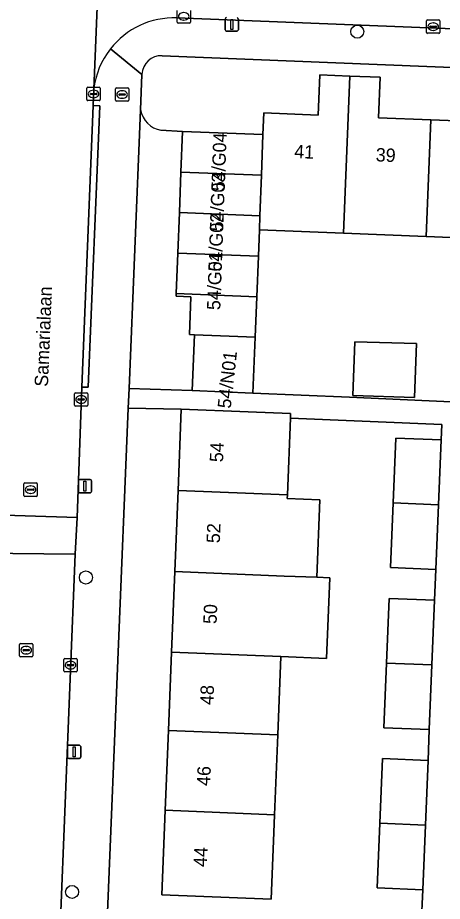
# Model space of a CAD drawing. Extents: x 161354 to 162026, y 386504 to 387460.
# Drawn here: x 161514.1 to 161545.9, y 387060.8 to 387126.9 of the extents above; entities that cross this region are included whole.
import ezdxf

# ---------------------------------------------------------------- set-up
doc = ezdxf.new("R2010")
doc.units = 0
for name, color, linetype in [('IMGEO_Boom', 7, 'Continuous'), ('IMGEO_Brandkraan', 7, 'Continuous'), ('IMGEO_Erf', 7, 'Continuous'), ('IMGEO_Kolk', 7, 'Continuous'), ('IMGEO_Lichtmast', 7, 'Continuous'), ('IMGEO_Openbare_ruimte_label', 7, 'Continuous'), ('IMGEO_Pand', 7, 'Continuous'), ('IMGEO_Pand_nummerreeks', 7, 'Continuous'), ('IMGEO_Rijbaan_lokaal_open', 7, 'Continuous'), ('IMGEO_Rioolput', 7, 'Continuous'), ('IMGEO_Voetpad_open', 7, 'Continuous')]:
    doc.layers.add(name, color=color, linetype=linetype)

msp = doc.modelspace()

# ---------------------------------------------------------------- linework, layer by layer
at = {"layer": 'IMGEO_Boom'}
for centre in [(161539.507, 387125.881), (161519.186, 387085.044), (161518.148, 387061.52)]:
    msp.add_circle(centre, 0.489, dxfattribs=at)
at = {"layer": 'IMGEO_Brandkraan'}
for p, q in [((161521.471, 387121.677), (161522.323, 387121.677)), ((161521.396, 387120.751), (161521.396, 387121.603)), ((161521.655, 387121.171), (161521.655, 387121.183)), ((161522.093, 387121.134), (161521.695, 387121.134)), ((161521.698, 387121.22), (161522.096, 387121.22)), ((161521.884, 387121.457), (161521.909, 387121.457)), ((161522.139, 387121.183), (161522.139, 387121.171)), ((161522.397, 387121.603), (161522.397, 387120.751)), ((161522.323, 387120.677), (161521.471, 387120.677)), ((161521.907, 387120.897), (161521.882, 387120.897))]:
    msp.add_line(p, q, dxfattribs=at)
for points in [[(161521.471, 387121.677), (161522.323, 387121.677)], [(161521.396, 387120.751), (161521.396, 387121.603)], [(161522.397, 387121.603), (161522.397, 387120.751)], [(161522.323, 387120.677), (161521.471, 387120.677)]]:
    msp.add_lwpolyline(points, dxfattribs=at)
for centre, radius, start, end in [((161521.473, 387121.601), 0.0765, 91.55205, 178.44795), ((161521.473, 387121.601), 0.0765, 91.55205, 178.44795), ((161522.321, 387121.601), 0.0765, 1.55205, 88.44795), ((161522.321, 387121.601), 0.0765, 1.55205, 88.44795), ((161521.695, 387121.18), 0.0403, 85.87752, 175.75265), ((161521.692, 387121.17), 0.0366, 178.93798, 274.71019), ((161522.096, 387121.177), 0.043, 264.86636, 352.45326), ((161522.1, 387121.182), 0.0386, 1.73085, 96.63898), ((161521.473, 387120.753), 0.0765, 181.55205, 268.44795), ((161521.473, 387120.753), 0.0765, 181.55205, 268.44795), ((161522.321, 387120.753), 0.0765, 271.55205, 358.44795), ((161522.321, 387120.753), 0.0765, 271.55205, 358.44795)]:
    msp.add_arc(centre, radius, start, end, dxfattribs=at)
for centre, major_axis, ratio, start_param, end_param in [((161521.883, 387121.177), (-0.387, 0.002), 0.722429, 4.712389, 7.853982), ((161521.908, 387121.177), (-0.39, 0.002), 0.717154, 1.570796, 4.712389)]:
    msp.add_ellipse(centre, major_axis=major_axis, ratio=ratio, start_param=start_param, end_param=end_param, dxfattribs=at)
at = {"layer": 'IMGEO_Erf'}
for points in [[(161607.248, 387120.747), (161524.9, 387124.083)], [(161523.384, 387122.688), (161523.275, 387120.032)], [(161524.801, 387118.502), (161526.428, 387118.418), (161532.445, 387118.176), (161532.513, 387119.807), (161536.573, 387119.644), (161536.694, 387122.652), (161538.952, 387122.561), (161541.209, 387122.47), (161541.087, 387119.445), (161545.005, 387119.288), (161548.923, 387119.13), (161549.045, 387122.166), (161551.292, 387122.075), (161553.539, 387121.985), (161553.417, 387118.951), (161557.35, 387118.793), (161561.284, 387118.635), (161561.407, 387121.696)], [(161581.68, 387109.068), (161575.525, 387109.316), (161569.368, 387109.563), (161563.19, 387109.812), (161556.999, 387110.061), (161554.637, 387110.156), (161554.514, 387107.096), (161550.695, 387107.25), (161550.818, 387110.309), (161544.654, 387110.557), (161538.479, 387110.806), (161532.18, 387111.059), (161532.101, 387109.083), (161531.979, 387106.052), (161531.857, 387103.021), (161531.689, 387098.848), (161538.919, 387098.528), (161547.059, 387098.161), (161547.177, 387101.182), (161550.075, 387101.069), (161549.957, 387098.047), (161567.776, 387097.249), (161585.787, 387096.692)], [(161544.294, 387059.047), (161544.402, 387061.685), (161541.005, 387061.824), (161541.204, 387066.661), (161541.403, 387071.507), (161544.8, 387071.368), (161544.894, 387073.666), (161541.497, 387073.806), (161541.695, 387078.643), (161541.894, 387083.478), (161545.291, 387083.339), (161545.386, 387085.648), (161541.989, 387085.787), (161542.187, 387090.627), (161542.386, 387095.473), (161545.783, 387095.333), (161545.831, 387096.504), (161534.5, 387096.963), (161534.27, 387091.239), (161534.259, 387090.964), (161536.71, 387090.866), (161536.477, 387085.059), (161537.45, 387085.02), (161537.209, 387078.993), (161533.785, 387079.13), (161533.55, 387073.273), (161533.311, 387067.302), (161533.258, 387065.977), (161533.058, 387060.981), (161524.876, 387061.309), (161525.129, 387067.63), (161525.368, 387073.601), (161525.603, 387079.458), (161525.844, 387085.485), (161526.088, 387091.567), (161526.331, 387097.645), (161522.356, 387097.725), (161520.801, 387060.002)]]:
    msp.add_lwpolyline(points, dxfattribs=at)
msp.add_lwpolyline([(161543.779, 387098.504), (161539.175, 387098.672), (161539.321, 387102.683), (161543.927, 387102.555)], close=True, dxfattribs=at)
for centre, radius, start, end in [((161524.84, 387122.627), 1.457, 87.64736, 177.59221), ((161525.138, 387120.364), 1.893, 190.11447, 259.73554)]:
    msp.add_arc(centre, radius, start, end, dxfattribs=at)
at = {"layer": 'IMGEO_Kolk'}
for p, q in [((161526.013, 387126.602), (161526.013, 387127.454)), ((161527.014, 387127.454), (161527.014, 387126.602)), ((161526.94, 387126.528), (161526.088, 387126.528)), ((161526.524, 387126.748), (161526.499, 387126.748)), ((161544.689, 387125.83), (161544.689, 387126.682)), ((161544.764, 387126.756), (161545.616, 387126.756)), ((161544.948, 387126.25), (161544.948, 387126.262)), ((161544.991, 387126.299), (161545.389, 387126.299)), ((161545.177, 387126.536), (161545.202, 387126.536)), ((161545.432, 387126.262), (161545.432, 387126.25)), ((161545.69, 387126.682), (161545.69, 387125.83)), ((161545.616, 387125.756), (161544.764, 387125.756)), ((161545.386, 387126.213), (161544.988, 387126.213)), ((161545.2, 387125.976), (161545.175, 387125.976)), ((161519.26, 387120.795), (161519.26, 387121.647)), ((161519.335, 387121.721), (161520.187, 387121.721)), ((161520.261, 387121.647), (161520.261, 387120.795)), ((161519.519, 387121.215), (161519.519, 387121.227)), ((161519.957, 387121.178), (161519.559, 387121.178)), ((161519.562, 387121.264), (161519.96, 387121.264)), ((161519.748, 387121.501), (161519.773, 387121.501)), ((161520.003, 387121.227), (161520.003, 387121.215)), ((161520.187, 387120.721), (161519.335, 387120.721)), ((161519.771, 387120.941), (161519.746, 387120.941)), ((161518.329, 387097.941), (161518.329, 387098.793)), ((161518.404, 387098.867), (161519.256, 387098.867)), ((161518.817, 387098.647), (161518.842, 387098.647)), ((161519.33, 387098.793), (161519.33, 387097.941)), ((161519.256, 387097.867), (161518.404, 387097.867)), ((161518.588, 387098.361), (161518.588, 387098.373)), ((161519.026, 387098.324), (161518.628, 387098.324)), ((161518.631, 387098.41), (161519.029, 387098.41)), ((161518.84, 387098.087), (161518.815, 387098.087)), ((161519.072, 387098.373), (161519.072, 387098.361)), ((161517.533, 387078.067), (161517.533, 387078.919)), ((161517.608, 387078.993), (161518.46, 387078.993)), ((161518.021, 387078.773), (161518.046, 387078.773)), ((161518.534, 387078.919), (161518.534, 387078.067)), ((161518.46, 387077.993), (161517.608, 387077.993)), ((161517.792, 387078.487), (161517.792, 387078.499)), ((161518.23, 387078.45), (161517.832, 387078.45)), ((161517.835, 387078.536), (161518.233, 387078.536)), ((161518.044, 387078.213), (161518.019, 387078.213)), ((161518.276, 387078.499), (161518.276, 387078.487))]:
    msp.add_line(p, q, dxfattribs=at)
for points in [[(161526.013, 387126.602), (161526.013, 387127.454)], [(161527.014, 387127.454), (161527.014, 387126.602)], [(161526.94, 387126.528), (161526.088, 387126.528)], [(161544.689, 387125.83), (161544.689, 387126.682)], [(161544.764, 387126.756), (161545.616, 387126.756)], [(161545.69, 387126.682), (161545.69, 387125.83)], [(161545.616, 387125.756), (161544.764, 387125.756)], [(161519.26, 387120.795), (161519.26, 387121.647)], [(161519.335, 387121.721), (161520.187, 387121.721)], [(161520.261, 387121.647), (161520.261, 387120.795)], [(161520.187, 387120.721), (161519.335, 387120.721)], [(161518.329, 387097.941), (161518.329, 387098.793)], [(161518.404, 387098.867), (161519.256, 387098.867)], [(161519.33, 387098.793), (161519.33, 387097.941)], [(161519.256, 387097.867), (161518.404, 387097.867)], [(161517.533, 387078.067), (161517.533, 387078.919)], [(161517.608, 387078.993), (161518.46, 387078.993)], [(161518.534, 387078.919), (161518.534, 387078.067)], [(161518.46, 387077.993), (161517.608, 387077.993)]]:
    msp.add_lwpolyline(points, dxfattribs=at)
for centre, radius, start, end in [((161526.09, 387126.604), 0.0765, 181.55205, 268.44795), ((161526.09, 387126.604), 0.0765, 181.55205, 268.44795), ((161526.938, 387126.604), 0.0765, 271.55205, 358.44795), ((161526.938, 387126.604), 0.0765, 271.55205, 358.44795), ((161544.766, 387126.68), 0.0765, 91.55205, 178.44795), ((161544.766, 387126.68), 0.0765, 91.55205, 178.44795), ((161544.988, 387126.259), 0.0403, 85.87752, 175.75265), ((161544.985, 387126.249), 0.0366, 178.93798, 274.71019), ((161545.389, 387126.256), 0.043, 264.86636, 352.45326), ((161545.393, 387126.261), 0.0386, 1.73085, 96.63898), ((161545.614, 387126.68), 0.0765, 1.55205, 88.44795), ((161545.614, 387126.68), 0.0765, 1.55205, 88.44795), ((161544.766, 387125.832), 0.0765, 181.55205, 268.44795), ((161544.766, 387125.832), 0.0765, 181.55205, 268.44795), ((161545.614, 387125.832), 0.0765, 271.55205, 358.44795), ((161545.614, 387125.832), 0.0765, 271.55205, 358.44795), ((161519.337, 387121.645), 0.0765, 91.55205, 178.44795), ((161519.337, 387121.645), 0.0765, 91.55205, 178.44795), ((161520.185, 387121.645), 0.0765, 1.55205, 88.44795), ((161520.185, 387121.645), 0.0765, 1.55205, 88.44795), ((161519.559, 387121.224), 0.0403, 85.87752, 175.75265), ((161519.556, 387121.214), 0.0366, 178.93798, 274.71019), ((161519.96, 387121.221), 0.043, 264.86636, 352.45326), ((161519.964, 387121.226), 0.0386, 1.73085, 96.63898), ((161519.337, 387120.797), 0.0765, 181.55205, 268.44795), ((161519.337, 387120.797), 0.0765, 181.55205, 268.44795), ((161520.185, 387120.797), 0.0765, 271.55205, 358.44795), ((161520.185, 387120.797), 0.0765, 271.55205, 358.44795), ((161518.406, 387098.791), 0.0765, 91.55205, 178.44795), ((161518.406, 387098.791), 0.0765, 91.55205, 178.44795), ((161519.254, 387098.791), 0.0765, 1.55205, 88.44795), ((161519.254, 387098.791), 0.0765, 1.55205, 88.44795), ((161518.406, 387097.943), 0.0765, 181.55205, 268.44795), ((161518.406, 387097.943), 0.0765, 181.55205, 268.44795), ((161518.628, 387098.37), 0.0403, 85.87752, 175.75265), ((161518.625, 387098.36), 0.0366, 178.93798, 274.71019), ((161519.029, 387098.367), 0.043, 264.86636, 352.45326), ((161519.033, 387098.372), 0.0386, 1.73085, 96.63898), ((161519.254, 387097.943), 0.0765, 271.55205, 358.44795), ((161519.254, 387097.943), 0.0765, 271.55205, 358.44795), ((161517.61, 387078.917), 0.0765, 91.55205, 178.44795), ((161517.61, 387078.917), 0.0765, 91.55205, 178.44795), ((161518.458, 387078.917), 0.0765, 1.55205, 88.44795), ((161518.458, 387078.917), 0.0765, 1.55205, 88.44795), ((161517.61, 387078.069), 0.0765, 181.55205, 268.44795), ((161517.61, 387078.069), 0.0765, 181.55205, 268.44795), ((161517.832, 387078.496), 0.0403, 85.87752, 175.75265), ((161517.829, 387078.486), 0.0366, 178.93798, 274.71019), ((161518.233, 387078.493), 0.043, 264.86636, 352.45326), ((161518.237, 387078.498), 0.0386, 1.73085, 96.63898), ((161518.458, 387078.069), 0.0765, 271.55205, 358.44795), ((161518.458, 387078.069), 0.0765, 271.55205, 358.44795)]:
    msp.add_arc(centre, radius, start, end, dxfattribs=at)
for centre, major_axis, ratio, start_param, end_param in [((161526.5, 387127.028), (-0.387, 0.002), 0.722429, 4.712389, 7.853982), ((161526.525, 387127.028), (-0.39, 0.002), 0.717154, 1.570796, 4.712389), ((161545.176, 387126.256), (-0.387, 0.002), 0.722429, 4.712389, 7.853982), ((161545.201, 387126.256), (-0.39, 0.002), 0.717154, 1.570796, 4.712389), ((161519.747, 387121.221), (-0.387, 0.002), 0.722429, 4.712389, 7.853982), ((161519.772, 387121.221), (-0.39, 0.002), 0.717154, 1.570796, 4.712389), ((161518.816, 387098.367), (-0.387, 0.002), 0.722429, 4.712389, 7.853982), ((161518.841, 387098.367), (-0.39, 0.002), 0.717154, 1.570796, 4.712389), ((161518.02, 387078.493), (-0.387, 0.002), 0.722429, 4.712389, 7.853982), ((161518.045, 387078.493), (-0.39, 0.002), 0.717154, 1.570796, 4.712389)]:
    msp.add_ellipse(centre, major_axis=major_axis, ratio=ratio, start_param=start_param, end_param=end_param, dxfattribs=at)
at = {"layer": 'IMGEO_Lichtmast'}
for p, q in [((161529.61, 387126.028), (161529.61, 387126.828)), ((161529.61, 387126.828), (161529.61, 387126.028)), ((161530.6, 387126.828), (161530.6, 387126.028)), ((161530.6, 387126.028), (161530.6, 387126.828)), ((161530.5, 387125.928), (161529.71, 387125.928)), ((161529.71, 387125.928), (161530.5, 387125.928)), ((161518.62, 387091.49), (161518.62, 387092.29)), ((161518.62, 387092.29), (161518.62, 387091.49)), ((161518.72, 387092.39), (161519.51, 387092.39)), ((161519.51, 387092.39), (161518.72, 387092.39)), ((161519.61, 387092.29), (161519.61, 387091.49)), ((161519.61, 387091.49), (161519.61, 387092.29)), ((161519.51, 387091.39), (161518.72, 387091.39)), ((161518.72, 387091.39), (161519.51, 387091.39)), ((161517.805, 387071.593), (161517.805, 387072.393)), ((161517.805, 387072.393), (161517.805, 387071.593)), ((161517.905, 387072.493), (161518.695, 387072.493)), ((161518.695, 387072.493), (161517.905, 387072.493)), ((161518.795, 387072.393), (161518.795, 387071.593)), ((161518.795, 387071.593), (161518.795, 387072.393)), ((161518.695, 387071.493), (161517.905, 387071.493)), ((161517.905, 387071.493), (161518.695, 387071.493))]:
    msp.add_line(p, q, dxfattribs=at)
for points in [[(161530.03, 387126.803), (161530.18, 387126.803), (161530.18, 387126.053), (161530.03, 387126.053), (161530.03, 387126.803)], [(161519.04, 387092.265), (161519.19, 387092.265), (161519.19, 387091.515), (161519.04, 387091.515), (161519.04, 387092.265)], [(161518.225, 387072.368), (161518.375, 387072.368), (161518.375, 387071.618), (161518.225, 387071.618), (161518.225, 387072.368)]]:
    msp.add_lwpolyline(points, dxfattribs=at)
for centre, start, end in [((161529.71, 387126.828), 90, 180), ((161529.71, 387126.828), 90, 180), ((161530.5, 387126.828), 0, 90), ((161530.5, 387126.828), 360, 90), ((161529.71, 387126.028), 180, 270), ((161529.71, 387126.028), 180, 270), ((161530.5, 387126.028), 270, 0), ((161530.5, 387126.028), 270, 0), ((161518.72, 387092.29), 90, 180), ((161518.72, 387092.29), 90, 180), ((161519.51, 387092.29), 0, 90), ((161519.51, 387092.29), 360, 90), ((161518.72, 387091.49), 180, 270), ((161518.72, 387091.49), 180, 270), ((161519.51, 387091.49), 270, 0), ((161519.51, 387091.49), 270, 0), ((161517.905, 387072.393), 90, 180), ((161517.905, 387072.393), 90, 180), ((161518.695, 387072.393), 0, 90), ((161518.695, 387072.393), 360, 90), ((161517.905, 387071.593), 180, 270), ((161517.905, 387071.593), 180, 270), ((161518.695, 387071.593), 270, 0), ((161518.695, 387071.593), 270, 0)]:
    msp.add_arc(centre, 0.1, start, end, dxfattribs=at)
at = {"layer": 'IMGEO_Pand'}
for points in [[(161532.219, 387112.114), (161532.18, 387111.059), (161538.479, 387110.806), (161538.952, 387122.561), (161536.694, 387122.652), (161536.573, 387119.644), (161532.513, 387119.807), (161532.445, 387118.176), (161532.332, 387115.145)], [(161538.479, 387110.806), (161544.654, 387110.557), (161545.005, 387119.288), (161541.087, 387119.445), (161541.209, 387122.47), (161538.952, 387122.561)], [(161551.292, 387122.075), (161549.045, 387122.166), (161548.923, 387119.13), (161545.005, 387119.288), (161544.654, 387110.557), (161550.818, 387110.309)], [(161526.306, 387115.379), (161532.332, 387115.145), (161532.445, 387118.176), (161526.428, 387118.418)], [(161532.219, 387112.114), (161532.332, 387115.145), (161526.306, 387115.379), (161526.184, 387112.348)], [(161532.101, 387109.083), (161532.18, 387111.059), (161532.219, 387112.114), (161526.184, 387112.348), (161526.062, 387109.317)], [(161526.062, 387109.317), (161525.94, 387106.286), (161531.979, 387106.052), (161532.101, 387109.083)], [(161531.857, 387103.021), (161531.979, 387106.052), (161525.94, 387106.286), (161525.932, 387106.085), (161527.05, 387106.041), (161526.936, 387103.218), (161527.308, 387103.203)], [(161527.308, 387103.203), (161527.141, 387099.031), (161531.689, 387098.848), (161531.857, 387103.021)], [(161539.175, 387098.672), (161543.779, 387098.504), (161543.927, 387102.555), (161539.321, 387102.683)], [(161534.5, 387096.963), (161534.514, 387097.317), (161531.327, 387097.445), (161526.331, 387097.645), (161526.088, 387091.567), (161534.27, 387091.239)], [(161545.783, 387095.333), (161542.386, 387095.473), (161542.187, 387090.627), (161545.584, 387090.487)], [(161534.27, 387091.239), (161526.088, 387091.567), (161525.844, 387085.485), (161534.027, 387085.157), (161536.477, 387085.059), (161536.71, 387090.866), (161534.259, 387090.964)], [(161545.584, 387090.487), (161542.187, 387090.627), (161541.989, 387085.787), (161545.386, 387085.648)], [(161536.477, 387085.059), (161534.027, 387085.157), (161525.844, 387085.485), (161525.603, 387079.458), (161533.785, 387079.13), (161537.209, 387078.993), (161537.45, 387085.02)], [(161545.291, 387083.339), (161541.894, 387083.478), (161541.695, 387078.643), (161545.093, 387078.503)], [(161533.55, 387073.273), (161533.785, 387079.13), (161525.603, 387079.458), (161525.368, 387073.601)], [(161545.093, 387078.503), (161541.695, 387078.643), (161541.497, 387073.806), (161544.894, 387073.666)], [(161525.368, 387073.601), (161525.129, 387067.63), (161533.311, 387067.302), (161533.55, 387073.273)], [(161544.8, 387071.368), (161541.403, 387071.507), (161541.204, 387066.661), (161544.601, 387066.522)], [(161525.129, 387067.63), (161524.876, 387061.309), (161533.058, 387060.981), (161533.258, 387065.977), (161533.311, 387067.302)], [(161544.601, 387066.522), (161541.204, 387066.661), (161541.005, 387061.824), (161544.402, 387061.685)]]:
    msp.add_lwpolyline(points, close=True, dxfattribs=at)
at = {"layer": 'IMGEO_Rijbaan_lokaal_open'}
for points in [[(161519.725, 387120.348), (161519.774, 387121.572), (161520.445, 387138.15), (161520.472, 387138.311), (161520.812, 387145.699), (161513.739, 387145.846), (161513.191, 387130.059), (161512.919, 387123.336), (161511.482, 387089.761), (161518.541, 387089.529), (161518.878, 387099.285)], [(161518.541, 387089.529), (161511.482, 387089.761), (161511.352, 387086.863), (161518.375, 387086.785)], [(161517.25, 387058.822), (161518.375, 387086.785), (161511.352, 387086.863), (161511.261, 387082.272), (161511.056, 387077.183), (161510.258, 387057.427), (161510.001, 387051.057), (161508.97, 387025.525), (161508.486, 387013.528), (161515.367, 387013.247), (161515.696, 387021.395), (161516.407, 387038.998), (161516.445, 387039.933), (161516.423, 387040.443), (161517.194, 387058.372)]]:
    msp.add_lwpolyline(points, close=True, dxfattribs=at)
for points in [[(161520.472, 387138.311), (161520.445, 387138.15), (161519.774, 387121.572)], [(161525.989, 387126.911), (161609.444, 387123.591), (161627.105, 387122.855), (161628.6, 387122.785)]]:
    msp.add_lwpolyline(points, dxfattribs=at)
for centre, radius, start, end in [((161525.786, 387120.862), 6.052, 88.0741, 141.94327), ((161525.78, 387120.862), 6.048, 141.91311, 173.25986)]:
    msp.add_arc(centre, radius, start, end, dxfattribs=at)
at = {"layer": 'IMGEO_Rioolput'}
for p, q in [((161514.547, 387091.192), (161514.547, 387092.044)), ((161514.622, 387092.118), (161515.474, 387092.118)), ((161515.035, 387091.898), (161515.06, 387091.898)), ((161515.548, 387092.044), (161515.548, 387091.192)), ((161514.806, 387091.612), (161514.806, 387091.624)), ((161515.244, 387091.575), (161514.846, 387091.575)), ((161514.849, 387091.661), (161515.247, 387091.661)), ((161515.058, 387091.338), (161515.033, 387091.338)), ((161515.29, 387091.624), (161515.29, 387091.612)), ((161515.474, 387091.118), (161514.622, 387091.118)), ((161514.215, 387079.186), (161514.215, 387080.038)), ((161514.29, 387080.112), (161515.142, 387080.112)), ((161515.216, 387080.038), (161515.216, 387079.186)), ((161514.474, 387079.606), (161514.474, 387079.618)), ((161514.912, 387079.569), (161514.514, 387079.569)), ((161514.517, 387079.655), (161514.915, 387079.655)), ((161514.726, 387079.332), (161514.701, 387079.332)), ((161514.703, 387079.892), (161514.728, 387079.892)), ((161514.958, 387079.618), (161514.958, 387079.606)), ((161515.142, 387079.112), (161514.29, 387079.112))]:
    msp.add_line(p, q, dxfattribs=at)
for points in [[(161514.547, 387091.192), (161514.547, 387092.044)], [(161514.622, 387092.118), (161515.474, 387092.118)], [(161515.548, 387092.044), (161515.548, 387091.192)], [(161515.474, 387091.118), (161514.622, 387091.118)], [(161514.215, 387079.186), (161514.215, 387080.038)], [(161514.29, 387080.112), (161515.142, 387080.112)], [(161515.216, 387080.038), (161515.216, 387079.186)], [(161515.142, 387079.112), (161514.29, 387079.112)]]:
    msp.add_lwpolyline(points, dxfattribs=at)
for centre, radius, start, end in [((161514.624, 387092.042), 0.0765, 91.55205, 178.44795), ((161514.624, 387092.042), 0.0765, 91.55205, 178.44795), ((161515.472, 387092.042), 0.0765, 1.55205, 88.44795), ((161515.472, 387092.042), 0.0765, 1.55205, 88.44795), ((161514.846, 387091.621), 0.0403, 85.87752, 175.75265), ((161514.843, 387091.611), 0.0366, 178.93798, 274.71019), ((161515.247, 387091.618), 0.043, 264.86636, 352.45326), ((161515.251, 387091.623), 0.0386, 1.73085, 96.63898), ((161514.624, 387091.194), 0.0765, 181.55205, 268.44795), ((161514.624, 387091.194), 0.0765, 181.55205, 268.44795), ((161515.472, 387091.194), 0.0765, 271.55205, 358.44795), ((161515.472, 387091.194), 0.0765, 271.55205, 358.44795), ((161514.292, 387080.036), 0.0765, 91.55205, 178.44795), ((161514.292, 387080.036), 0.0765, 91.55205, 178.44795), ((161515.14, 387080.036), 0.0765, 1.55205, 88.44795), ((161515.14, 387080.036), 0.0765, 1.55205, 88.44795), ((161514.514, 387079.615), 0.0403, 85.87752, 175.75265), ((161514.511, 387079.605), 0.0366, 178.93798, 274.71019), ((161514.915, 387079.612), 0.043, 264.86636, 352.45326), ((161514.919, 387079.617), 0.0386, 1.73085, 96.63898), ((161514.292, 387079.188), 0.0765, 181.55205, 268.44795), ((161514.292, 387079.188), 0.0765, 181.55205, 268.44795), ((161515.14, 387079.188), 0.0765, 271.55205, 358.44795), ((161515.14, 387079.188), 0.0765, 271.55205, 358.44795)]:
    msp.add_arc(centre, radius, start, end, dxfattribs=at)
for centre, major_axis, ratio, start_param, end_param in [((161515.034, 387091.618), (-0.387, 0.002), 0.722429, 4.712389, 7.853982), ((161515.059, 387091.618), (-0.39, 0.002), 0.717154, 1.570796, 4.712389), ((161514.702, 387079.612), (-0.387, 0.002), 0.722429, 4.712389, 7.853982), ((161514.727, 387079.612), (-0.39, 0.002), 0.717154, 1.570796, 4.712389)]:
    msp.add_ellipse(centre, major_axis=major_axis, ratio=ratio, start_param=start_param, end_param=end_param, dxfattribs=at)
at = {"layer": 'IMGEO_Voetpad_open'}
for points in [[(161609.444, 387123.591), (161525.989, 387126.911)], [(161522.356, 387097.725), (161522.416, 387099.184), (161523.275, 387120.032), (161523.384, 387122.688), (161521.02, 387124.593)], [(161521.02, 387124.593), (161523.384, 387122.688)], [(161524.9, 387124.083), (161607.248, 387120.747), (161608.808, 387120.684), (161628.95, 387119.868)], [(161519.774, 387121.572), (161519.725, 387120.348), (161520.223, 387120.336), (161519.365, 387099.273), (161518.878, 387099.285), (161518.541, 387089.529), (161518.375, 387086.785), (161517.25, 387058.822)], [(161523.275, 387120.032), (161522.416, 387099.184), (161527.141, 387099.031), (161527.308, 387103.203), (161526.936, 387103.218), (161527.05, 387106.041), (161525.932, 387106.085), (161525.94, 387106.286), (161526.062, 387109.317), (161526.184, 387112.348), (161526.306, 387115.379), (161526.428, 387118.418), (161524.801, 387118.502)], [(161547.059, 387098.161), (161538.919, 387098.528), (161531.689, 387098.848), (161527.141, 387099.031), (161522.416, 387099.184), (161522.356, 387097.725), (161526.331, 387097.645), (161531.327, 387097.445), (161534.514, 387097.317), (161534.5, 387096.963), (161545.831, 387096.504), (161545.783, 387095.333), (161545.584, 387090.487), (161545.386, 387085.648), (161545.291, 387083.339), (161545.093, 387078.503), (161544.894, 387073.666), (161544.8, 387071.368), (161544.601, 387066.522), (161544.402, 387061.685), (161544.294, 387059.047)], [(161518.836, 387054.51), (161520.801, 387060.002), (161522.356, 387097.725)]]:
    msp.add_lwpolyline(points, dxfattribs=at)
msp.add_lwpolyline([(161518.878, 387099.285), (161519.365, 387099.273), (161520.223, 387120.336), (161519.725, 387120.348)], close=True, dxfattribs=at)
for centre, radius, start, end in [((161525.786, 387120.862), 6.052, 88.0741, 141.94327), ((161525.78, 387120.862), 6.048, 141.91311, 173.25986), ((161524.84, 387122.627), 1.457, 87.64736, 177.59221), ((161525.138, 387120.364), 1.893, 190.11447, 259.73554)]:
    msp.add_arc(centre, radius, start, end, dxfattribs=at)

# ---------------------------------------------------------------- texts
at = {"layer": 'IMGEO_Openbare_ruimte_label'}
msp.add_text('Samarialaan', height=1, rotation=87.64984, dxfattribs=at).set_placement((161516.342, 387099.302))
at = {"layer": 'IMGEO_Pand_nummerreeks'}
for s, rotation, p in [('54/G04', 87.89963, (161529.571, 387113.933)), ('41', 357.65964, (161534.773, 387116.432)), ('39', 357.65964, (161540.873, 387116.183)), ('54/G03', 87.89963, (161529.461, 387110.931)), ('54/G02', 87.89963, (161529.351, 387107.923)), ('54/G01', 87.89963, (161529.245, 387105.038)), ('54/N01', 83.65981, (161530.03, 387097.652)), ('54', 87.70838, (161529.453, 387093.659)), ('52', 87.70838, (161529.211, 387087.6)), ('50', 87.70838, (161528.968, 387081.55)), ('48', 87.70693, (161528.726, 387075.495)), ('46', 87.70693, (161528.483, 387069.436)), ('44', 87.70693, (161528.241, 387063.38))]:
    msp.add_text(s, height=1, rotation=rotation, dxfattribs=at).set_placement(p)

doc.saveas('drawing.dxf')
